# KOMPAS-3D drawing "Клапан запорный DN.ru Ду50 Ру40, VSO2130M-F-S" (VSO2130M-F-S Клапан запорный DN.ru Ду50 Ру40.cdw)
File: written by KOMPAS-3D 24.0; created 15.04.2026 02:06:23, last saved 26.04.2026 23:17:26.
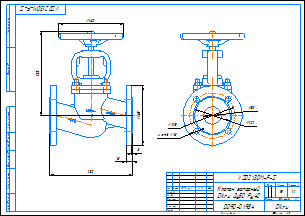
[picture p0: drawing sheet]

Document properties: Автор: DN.ru; Форматы листов документа: A3; Полное имя файла: VSO2130M-F-S Клапан запорный DN.ru Ду50 Ру40.m3d; Масса: 15; Наименование: Клапан запорный DN.ru Ду50 Ру40; Количество листов документа: 1; Примечание: D090-01984

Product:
- Part/product: Клапан запорный DN.ru Ду50 Ру40  | designation VSO2130M-F-S
    Масса: 15
    Раздел спецификации: Прочие изделия
    Примечание: D090-01984

Views: Вид 1, Вид:1, Проекционный вид 2
Referenced files in C:\Работа\VSO2130M-F-S Клапан запорный DN.ru\DN15\: VSO2130M-F-S DN15 PN40  Клапан запорный сильфонный DN.ru.m3d
Referenced files in C:\Работа\VSO2130M-F-S Клапан запорный DN.ru Ду-x Ру40\DN50\: VSO2130M-F-S Клапан запорный DN.ru Ду50 Ру40.m3d
Referenced files in C:\Program Files\ASCON\KOMPAS-3D v24\Templates\: Чертеж_DN.ru.cdt
Referenced files in C:\Работа\ГОТОВЫЕ ИСХОДНИКИ\VSO2130M-F-S Клапан запорный сальниковый DN.ru Ду15-100 Ру40\DN50\: VSO2130M-F-S Клапан запорный DN.ru Ду50 Ру40.m3d
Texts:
  VSO2130M-F-S
  Чертеж_DN.ru.cdt
  Клапан запорный
  DN.ru Ду50 Ру40
  Клапан запорный DN.ru Ду50 Ру40
  VSO2130M-F-S Клапан запорный DN.ru Ду50 Ру40
Dimensions and other numbers on the sheet: 0; 3; 2; 4; 165; 18; 233; 180; 230; 5; 50; 102; 125; 4 отв.; 1:2; 1; 15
